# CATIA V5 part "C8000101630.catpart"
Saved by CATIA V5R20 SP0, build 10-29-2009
Part number: C8000101630
Source: Unknown
Property "A": "30"
Property "ARTICLENO": "C8000101630"
Property "B": "13"
Property "BOMINFO": "C8000101630"
Property "C": "46"
Property "CA": "C8000101630"
Property "D1": "38"
Property "DES": "ROTATING EYEBOLT WITH RING Ton 1,12 M16x30"
Property "E": "50"
Property "H": "105"
Property "L": "30"
Property "LINA": "C8000101630"
Property "NB": "C8000101630"
Property "NBSYN": "$CODE."
Property "NN": "C800"
Property "NT": "Rotating eyebolt with ring"
Property "SIZE": "M16"
Property "SUPPLIER": "CF"
Property "SW": "30"
Property "WEIGHT": "530"
Property "WLL": "1.12"
Bounding box of the stored display mesh (mm): x -27.837 to 28, y -30 to 117.837, z -19 to 19
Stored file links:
  C:\Users\Utente\Desktop\3D files 800\C8000101630.catpart
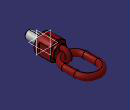
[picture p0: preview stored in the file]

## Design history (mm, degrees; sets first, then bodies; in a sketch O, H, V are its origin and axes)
Body1 "Geometry.1" (main body)
  Solid1 "C8000101630.catpart": solid without history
